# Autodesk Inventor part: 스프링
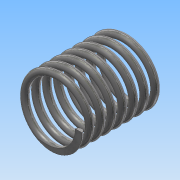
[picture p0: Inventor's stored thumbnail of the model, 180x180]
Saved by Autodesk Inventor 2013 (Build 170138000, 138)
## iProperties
Created: 2014-12
Part Number: 스프링
Material: 강철, 탄소
Document SubType Name: Modeling
Designer: Administrator
Density: 7.87 g/cm^3
Mass: 80.13 g
Surface Area: 103.216 cm^2
Volume: 10.1817 cm^3
Author: Administrator
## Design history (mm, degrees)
sketch "스케치1"
  geometry: L1 (0, 0)-(0, 48.5); L2 (0, 0)-(17.5, 0); L3 (0, 48.5)-(13.705, 48.5); C1 r 2 at (17.5, 0)
  constraints: 6 end point, 1 centre point, 1 horizontal alignment, 1 parallel, 1 perpendicular, 1 vertical
  dimensions: "d0" = 48.5 distance of L1.start L1.end (derived); "d1" = 4 diameter of C1; "d2" = 35 diameter of L2.end L1
feature "코일1" sketch "스케치1" pitch "d3" = 10; turns "d5" = 7.5; dims "d4" = 48.5 (= d0), "d6" = 0, angle "d7" = 90 deg, angle "d8" = 90 deg, "d9" = 0, "d10" = 0
sketch "스케치2"
  geometry: L1 (48.5, 22.5)-(0, 22.5); L2 (0, 22.5)-(0, -22.5); L3 (0, -22.5)-(48.5, -22.5); L4 (48.5, -22.5)-(48.5, 22.5); 2 further points
  constraints: 8 end point, 2 coincident, 2 parallel, 1 horizontal, 1 midpoint, 1 perpendicular
  dimensions: "d11" = 45 distance of L1.end L2.end; "d13" = 48.5 distance of L2.end L3.end (derived)
extrude "돌출1" sketch "스케치2" stored distance "d14" = 10; taper "d15" = 0 deg
node "솔리드1"
